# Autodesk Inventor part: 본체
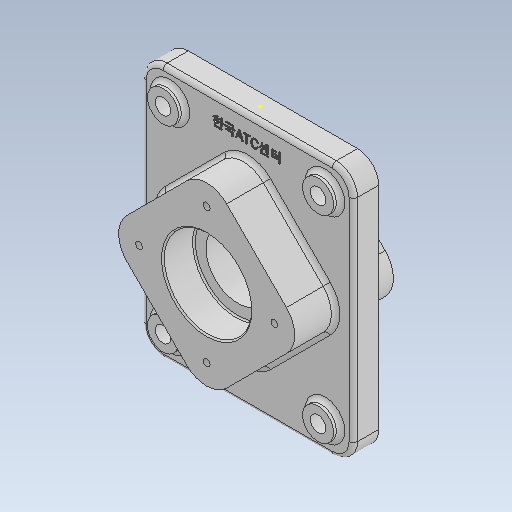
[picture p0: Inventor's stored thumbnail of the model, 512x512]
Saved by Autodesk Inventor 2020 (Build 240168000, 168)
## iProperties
Created: 2021-07
Part Number: 본체
Material: 일반
Document SubType Name: Modeling
Designer: Owner
Mass: 806.566 g
Surface Area: 962.824 cm^2
Volume: 806.566 cm^3
Density: 1 g/cm^3
Appearance: 기본값
Author: Owner
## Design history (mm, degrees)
sketch "스케치1"
  geometry: L1 (-75, -90)-(75, -90); L2 (75, -90)-(75, 90); L3 (75, 90)-(-75, 90); L4 (-75, 90)-(-75, -90); L5 (-75, -90)-(75, 90); L6 (75, -90)-(-75, 90); 1 further point
  constraints: 12 end point, 2 midpoint, 2 parallel, 1 horizontal, 1 perpendicular
  dimensions: "d0" = 150 distance of L3.end L2.end; "d1" = 180 distance of L2.end L1.end
extrude "돌출1" new body sketch "스케치1" stored distance "d2" = 18; taper "d3" = 0 deg
sketch "스케치2"
  geometry: L1 (0, -70.711)-(70.711, 0); L2 (70.711, 0)-(0, 70.711); L3 (0, 70.711)-(-70.711, 0); L4 (-70.711, 0)-(0, -70.711); L5 (0, -70.711)-(0, 70.711); L6 (70.711, 0)-(-70.711, 0); 4 further points
  constraints: 12 end point, 4 midpoint, 2 parallel, 1 coincident, 1 perpendicular, 1 vertical alignment
  dimensions: "d4" = 100 distance of L2.end L3.end; "d5" = 100 distance of L1.end L2.end
extrude "돌출2" join sketch "스케치2" distance "d6" = 29; taper "d7" = 0 deg
sketch "스케치3"
  geometry: L1 (0, 38)-(0, -35); L2 (31, 16)-(22.5, 16); L3 (70.711, -9)-(0, -9) reference; L4 (22.5, 16)-(22.5, -13); L5 (22.5, -13)-(31, -13); L6 (31, -13)-(31, -35); L7 (70.711, -35)-(0, -35) reference; L8 (31, 16)-(31, 38); L9 (70.711, 38)-(0, 38) reference; L10 (0, 9)-(0, 38) reference; L11 (31, 38)-(0, 38); L12 (0, -35)-(-70.711, -35) reference; L13 (31, -35)-(0, -35); 2 further points
  constraints: 16 end point, 3 perpendicular, 3 point on line, 3 vertical, 1 coincident, 1 collinear
  dimensions: "d10" = 22 distance of L5.end L6.end; "d11" = 22 distance of L2.start L8.end; "d12" = 62 diameter of L8 L1; "d13" = 62 diameter of L6 L1; "d16" = 45 diameter of L4 L1; "d17" = 8.5 distance of L2.start L2.end
revolve "회전1" sketch "스케치3" stored, may be unused: angle "d18" = 90 deg
sketch "스케치4" dims "d30" = 10
  geometry: L1 (-75, 90)-(-75, -90) reference; L2 (75, -90)-(75, 90) reference; L3 (75, 90)-(-75, 90) reference; C1 r 11 at (-55, 70); C2 r 11 at (55, 70); C3 r 11 at (-55, -70); C4 r 11 at (55, -70); 1 further point
  constraints: 4 centre point, 1 vertical, 4 other
  dimensions: "d19" = 22 diameter of C1; "d20" = 22 diameter of C2; "d21" = 110 distance of C2.centre C1.centre; "d22" = 20 distance from line of L1 C1.centre; "d23" = 20 distance from line of L2 C2.centre; "d24" = 20 distance from line of L3 C1.centre; "d27" = 140 distance of C1.centre C3.centre
extrude "돌출3" join sketch "스케치4" distance "d32" = 5; taper "d33" = 0 deg
sketch "스케치5"
  geometry: C1 r 11 at (0, 0) reference; C2 r 11 at (110, 0) reference; C3 r 11 at (110, -140) reference; C4 r 11 at (0, -140) reference; 5 further points
  constraints: 4 coincident
hole "구멍1" sketch "스케치5" at (0, 0), (110, 0), (110, -140), (0, -140) diameter "d34" = 11; stored, may be unused: countersink angle "d38" = 90 deg, drill point angle "d40" = 0 deg; dims "d35" = 8, "d36" = 4, "d37" = 2, "d39" = 30
fillet "모깎기1" dims "d41" = 20
fillet "모깎기2" dims "d42" = 3
fillet "모깎기3" dims "d43" = 15
fillet "모깎기4" dims "d44" = 3
fillet "모깎기5" dims "d45" = 3
sketch "스케치6"
  geometry: L1 (60, 90)-(-60, 90) reference; 2 further points
  constraints: 1 vertical alignment, 1 other
  dimensions: "d46" = 15 distance from line of point (0, 75) L1
feature "엠보싱1" sketch "스케치6" dims "d0" = 150, "d1" = 180, "d47" = 0.6, "d48" = 0
sketch "스케치7"
  geometry: 2 further points
  constraints: 1 vertical alignment
  dimensions: "d49" = 48 distance of point (0, 0) point (0, 48)
hole "구멍2" sketch "스케치7" at (0, 48) diameter "d50" = 4.917; stored, may be unused: countersink angle "d54" = 90 deg, drill point angle "d56" = 118 deg; dims "d51" = 10, "d52" = 4, "d53" = 2, "d55" = 13
fillet "모깎기8" dims "d62" = 1
chamfer "모따기1" distance "d63" = 1; stored, may be unused: second distance "d64" = 2, angle "d65" = 45 deg
sketch "스케치8"
  geometry: L1 (0, -70.711)-(70.711, 0); L2 (70.711, 0)-(0, 70.711); L3 (0, 70.711)-(-70.711, 0); L4 (-70.711, 0)-(0, -70.711); L5 (0, -70.711)-(0, 70.711); L6 (70.711, 0)-(-70.711, 0); 4 further points
  constraints: 12 end point, 4 midpoint, 2 parallel, 1 coincident, 1 horizontal alignment, 1 perpendicular, 1 vertical alignment
  dimensions: "d66" = 100 distance of L3.end L1.start
extrude "돌출4" join sketch "스케치8" distance "d67" = 23; taper "d68" = 0 deg
fillet "모깎기9" dims "d69" = 20
sketch "스케치9"
  geometry: 1 further point
sketch "스케치10"
  geometry: 2 further points
  constraints: 1 vertical alignment
  dimensions: "d70" = 48 distance of point (0, 0) point (0, 48)
hole "구멍3" sketch "스케치10" at (0, 48) diameter "d71" = 4.917; stored, may be unused: countersink angle "d75" = 90 deg, drill point angle "d77" = 118 deg; dims "d72" = 10, "d73" = 4, "d74" = 2, "d76" = 13
sketch "스케치11"
  geometry: C1 r 22.5 at (0, 0) reference; C2 r 31 at (0, 0); 1 further point
  constraints: 1 centre point, 1 coincident
  dimensions: "d78" = 62 diameter of C2
extrude "돌출5" cut sketch "스케치11" distance "d79" = 23; taper "d80" = 0 deg
fillet "모깎기10" dims "d81" = 1
chamfer "모따기2" distance "d82" = 1; stored, may be unused: second distance "d83" = 2, angle "d84" = 45 deg
fillet "모깎기11" dims "d88" = 3
node "솔리드1"
pattern_circular "원형 패턴1" dims angle "d58" = 360 deg
mirror "미러2"
pattern_circular "원형 패턴2" dims angle "d86" = 360 deg
feature "A9D066F2-1C7D-4E18-AEED-F7BC21143FA4" dims "d34" = 11, "d35" = 8, "d36" = 4, "d37" = 2, "d38" = 90 deg, "d39" = 30, "d40" = 0
